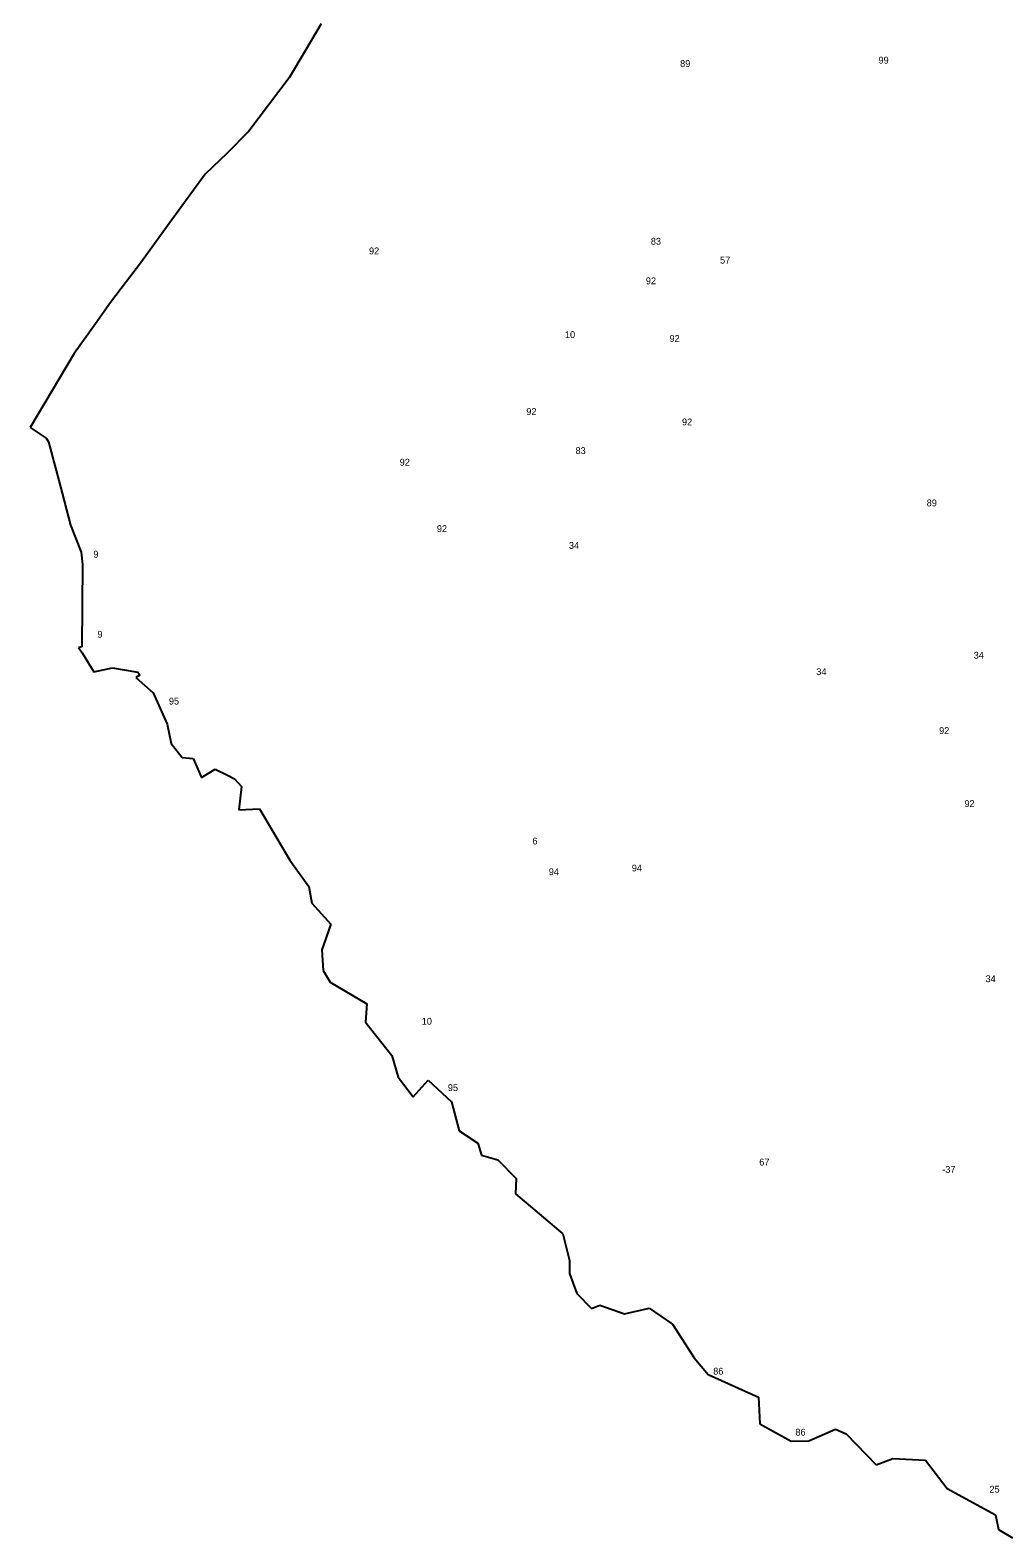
# Model space of a CAD drawing. Extents: x -783032 to -781233, y -975453 to -972360.
# Drawn here: x -783032 to -782209, y -975181 to -973909 of the extents above; entities that cross this region are included whole.
import ezdxf

# ---------------------------------------------------------------- set-up
doc = ezdxf.new("R2010")
doc.units = 0
doc.layers.add('Vrstva 13', color=7, linetype='Continuous')
doc.layers.add('Vrstva 24', color=7, linetype='Continuous')

msp = doc.modelspace()

# ---------------------------------------------------------------- linework, layer by layer
at = {"layer": 'Vrstva 13'}
for p, q in [((-782786.08, -973903.69), (-782813.2, -973949.16)), ((-782813.2, -973949.16), (-782847.27, -973994.21)), ((-782847.27, -973994.21), (-782865.49, -974012.65)), ((-782865.49, -974012.65), (-782884.12, -974030.35)), ((-782884.12, -974030.35), (-782914.45, -974072.14)), ((-782914.45, -974072.14), (-782937.75, -974104.3)), ((-782937.75, -974104.3), (-782963.73, -974138.58)), ((-782963.73, -974138.58), (-782976.57, -974156.6)), ((-782976.57, -974156.6), (-782994.48, -974181.77)), ((-782994.48, -974181.77), (-783031.56, -974244.21)), ((-783031.56, -974244.21), (-783018.18, -974253.13)), ((-783018.18, -974253.13), (-783015.99, -974256.32)), ((-783015.99, -974256.32), (-783006.16, -974292.93)), ((-783006.16, -974292.93), (-782997.42, -974326.45)), ((-782997.42, -974326.45), (-782988.5, -974349.31)), ((-782988.5, -974349.31), (-782987.43, -974359.65)), ((-782987.43, -974359.65), (-782987.95, -974429.05)), ((-782987.95, -974429.05), (-782990.87, -974429.64)), ((-782990.87, -974429.64), (-782987.78, -974434.33)), ((-782987.78, -974434.33), (-782977.95, -974450.36)), ((-782977.95, -974450.36), (-782962.24, -974446.93)), ((-782962.24, -974446.93), (-782940.87, -974450.63)), ((-782939.23, -974452.9), (-782942.33, -974454.91)), ((-782942.33, -974454.91), (-782927.85, -974468.02)), ((-782940.87, -974450.63), (-782939.23, -974452.9)), ((-782927.85, -974468.02), (-782915.92, -974494.35)), ((-782915.92, -974494.35), (-782912.54, -974510.57)), ((-782912.54, -974510.57), (-782903.53, -974522.41)), ((-782903.53, -974522.41), (-782894.15, -974523.33)), ((-782894.15, -974523.33), (-782886.96, -974539.45)), ((-782886.96, -974539.45), (-782875.5, -974532.34)), ((-782875.5, -974532.34), (-782865.12, -974537.44)), ((-782865.12, -974537.44), (-782859.21, -974540.54)), ((-782859.21, -974540.54), (-782853.51, -974546.82)), ((-782853.51, -974546.82), (-782855.64, -974566.59)), ((-782855.64, -974566.59), (-782838.25, -974565.68)), ((-782838.25, -974565.68), (-782812.61, -974609.04)), ((-782812.61, -974609.04), (-782796.54, -974631.35)), ((-782796.54, -974631.35), (-782793.99, -974645.47)), ((-782793.99, -974645.47), (-782777.96, -974663.05)), ((-782777.96, -974663.05), (-782785.51, -974684.72)), ((-782785.51, -974684.72), (-782784.42, -974702.02)), ((-782784.42, -974702.02), (-782778.68, -974711.95)), ((-782778.68, -974711.95), (-782747.82, -974730.27)), ((-782747.82, -974730.27), (-782748.91, -974745.75)), ((-782748.91, -974745.75), (-782726.65, -974773.72)), ((-782726.65, -974773.72), (-782721.41, -974792.21)), ((-782721.41, -974792.21), (-782708.57, -974808.79)), ((-782708.57, -974808.79), (-782696.1, -974794.67)), ((-782696.1, -974794.67), (-782676.25, -974813.07)), ((-782676.25, -974813.07), (-782669.86, -974837.48)), ((-782669.86, -974837.48), (-782654.2, -974847.86)), ((-782654.2, -974847.86), (-782650.93, -974857.79)), ((-782650.93, -974857.79), (-782637.17, -974861.89)), ((-782637.17, -974861.89), (-782621.79, -974877.74)), ((-782621.79, -974877.74), (-782622.33, -974890.67)), ((-782622.33, -974890.67), (-782582.36, -974924.2)), ((-782582.36, -974924.2), (-782576.76, -974946.79)), ((-782576.76, -974946.79), (-782576.72, -974957.81)), ((-782576.72, -974957.81), (-782570.71, -974974.48)), ((-782570.71, -974974.48), (-782558.14, -974987.14)), ((-782558.14, -974987.14), (-782551.31, -974984.59)), ((-782551.31, -974984.59), (-782530.55, -974991.7)), ((-782530.55, -974991.7), (-782509.61, -974986.96)), ((-782509.61, -974986.96), (-782490.04, -975000.44)), ((-782490.04, -975000.44), (-782471.78, -975028.77)), ((-782471.78, -975028.77), (-782460, -975042.89)), ((-782460, -975042.89), (-782417.51, -975062.05)), ((-782417.51, -975062.05), (-782416.24, -975084.49)), ((-782416.24, -975084.49), (-782389.88, -975099.27)), ((-782374.93, -975098.82), (-782352.65, -975089.17)), ((-782352.65, -975089.17), (-782343.54, -975093.09)), ((-782389.88, -975099.27), (-782374.93, -975098.82)), ((-782343.54, -975093.09), (-782318.23, -975119.14)), ((-782318.23, -975119.14), (-782304.12, -975113.77)), ((-782304.12, -975113.77), (-782276.66, -975115.14)), ((-782276.66, -975115.14), (-782258.27, -975139)), ((-782258.27, -975139), (-782217.61, -975161.32)), ((-782217.61, -975161.32), (-782215.06, -975173.61)), ((-782215.06, -975173.61), (-782203.36, -975180.72))]:
    msp.add_line(p, q, dxfattribs=at)

# ---------------------------------------------------------------- texts
at = {"layer": 'Vrstva 24'}
for s, p in [('89', (-782483.536, -973940.002)), ('99', (-782316.289, -973937.182)), ('83', (-782508.243, -974089.912)), ('92', (-782745.876, -974098.062)), ('57', (-782449.875, -974105.832)), ('92', (-782512.436, -974123.272)), ('10', (-782580.672, -974168.662)), ('92', (-782492.486, -974171.942)), ('92', (-782613.236, -974233.562)), ('92', (-782481.986, -974242.322)), ('83', (-782571.703, -974266.502)), ('92', (-782719.976, -974276.282)), ('89', (-782275.656, -974310.622)), ('92', (-782688.646, -974332.302)), ('34', (-782577.298, -974346.462)), ('9', (-782978.266, -974353.882)), ('9', (-782974.806, -974421.412)), ('34', (-782236.028, -974439.112)), ('34', (-782368.738, -974452.972)), ('95', (-782914.586, -974477.822)), ('92', (-782265.166, -974502.642)), ('92', (-782243.816, -974564.262)), ('6', (-782608.076, -974595.832)), ('94', (-782594.292, -974621.742)), ('94', (-782524.292, -974618.592)), ('34', (-782226.008, -974711.962)), ('10', (-782701.372, -974747.902)), ('95', (-782679.386, -974803.822)), ('67', (-782416.828, -974866.662)), ('-37', (-782262.482, -974872.81)), ('86', (-782455.646, -975043.022)), ('86', (-782386.346, -975094.472)), ('25', (-782222.733, -975142.572))]:
    msp.add_text(s, height=5.76, dxfattribs=at).set_placement(p)

doc.saveas('drawing.dxf')
